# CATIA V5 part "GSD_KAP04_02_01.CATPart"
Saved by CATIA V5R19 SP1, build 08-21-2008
Part number: GSD_KAP04_02_01
Definition: Beispiel für Kapitel 4 zum Buch CATIA V5 Flächenmodellierung.
Description: Copyright (c) 2009 Maik Hertha IT Consultants
Bounding box of the stored display mesh (mm): x -55.611 to 55.611, y 0 to 0, z -30.965 to 136.522
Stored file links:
  \GSD_BUCH_UEBUNG\GSD_KAP04_02_01.CATPart
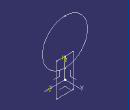
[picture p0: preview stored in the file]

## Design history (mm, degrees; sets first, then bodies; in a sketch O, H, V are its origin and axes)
AxisSystem1: origin (0, 0, 0), X (1, 0, 0), Y (0, 1, 0), Z (0, 0, 1)
Set1
  Sketch1 on ZX plane of AxisSystem1, origin (0, 0, 0), H (0, 0, 1), V (1, 0, 0)
    line L1 (-30.9653, 20.3026) -> (50.0981, 20.3026)
    line L2 (50.0981, 20.3026) -> (50.0981, -20.0663)
    line L3 (50.0981, -20.0663) -> (-30.9653, -20.0663)
    line L4 (-30.9653, -20.0663) -> (-30.9653, 20.3026)
    circle A1 centre (80.9112, 0) radius 55.6112
Body1 (main body)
